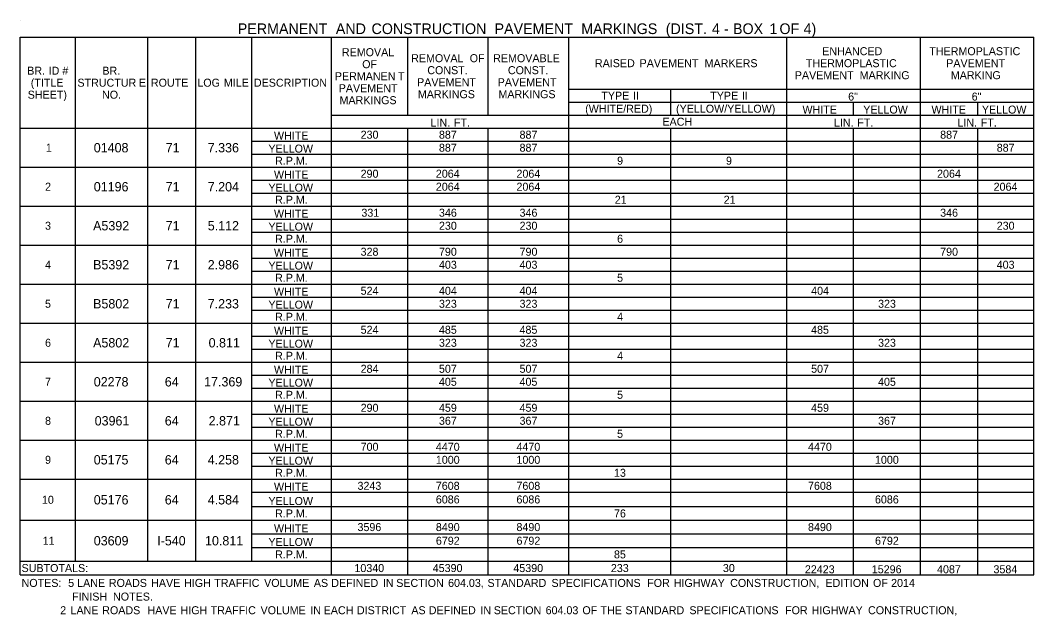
# Model space of a CAD drawing. Extents: x 540541 to 1930787, y -1948574 to 596640.
# Drawn here: x 540655 to 541415, y -1948048 to -1947601 of the extents above; entities that cross this region are included whole.
import ezdxf

# ---------------------------------------------------------------- set-up
doc = ezdxf.new("R2010")
doc.units = 0
doc.layers.add('Default', color=7, linetype='Continuous')
doc.layers.add('R_Border', color=7, linetype='Continuous')

msp = doc.modelspace()

# ---------------------------------------------------------------- linework, layer by layer
at = {"layer": 'Default'}
for p, q in [((540655.45, -1947614.17), (541415.47, -1947614.17)), ((540655.45, -1947614.17), (540888.97, -1947614.17)), ((540655.45, -1948017.33), (540655.45, -1947614.17)), ((540696.89, -1948007.1), (540696.89, -1947614.17)), ((540751, -1948007.1), (540751, -1947614.17)), ((540787.08, -1948007.1), (540787.08, -1947614.17)), ((540829, -1948007.1), (540829, -1947614.17)), ((540888.97, -1948017.33), (540888.97, -1947614.17)), ((540946, -1947614.17), (541066.9, -1947614.17)), ((540946, -1947672.67), (540946, -1947614.17)), ((541006.45, -1947672.67), (541006.45, -1947614.17)), ((541066.9, -1948017.33), (541066.9, -1947614.17)), ((541230.22, -1948017.33), (541230.22, -1947614.17)), ((541330.64, -1947672.67), (541330.64, -1947614.17)), ((541330.64, -1948017.33), (541330.64, -1947614.17)), ((541415.47, -1947653.17), (541415.47, -1947614.17)), ((541066.9, -1947653.17), (541415.47, -1947653.17)), ((541143.44, -1947672.67), (541143.44, -1947653.17)), ((541415.47, -1947672.67), (541415.47, -1947653.17)), ((541066.9, -1947662.92), (541415.47, -1947662.92)), ((541280.43, -1947672.67), (541280.43, -1947662.92)), ((541373.54, -1947672.67), (541373.54, -1947662.92)), ((540888.97, -1947672.67), (541415.47, -1947672.67)), ((541415.47, -1947682.42), (541415.47, -1947672.67)), ((540655.45, -1947682.42), (540829, -1947682.42)), ((540655.45, -1947682.42), (540787.08, -1947682.42)), ((540787.08, -1947682.42), (541415.47, -1947682.42)), ((540829, -1948007.1), (540829, -1947682.42)), ((540888.97, -1947701.92), (540888.97, -1947682.42)), ((540946, -1948007.1), (540946, -1947682.42)), ((540946, -1948017.33), (540946, -1947682.42)), ((541006.45, -1948007.1), (541006.45, -1947682.42)), ((541006.45, -1948017.33), (541006.45, -1947682.42)), ((541066.9, -1948007.1), (541066.9, -1947682.42)), ((541143.44, -1948017.33), (541143.44, -1947682.42)), ((541230.22, -1947731.17), (541230.22, -1947682.42)), ((541280.43, -1948007.1), (541280.43, -1947682.42)), ((541280.43, -1948017.33), (541280.43, -1947682.42)), ((541330.64, -1948007.1), (541330.64, -1947682.42)), ((541373.54, -1948017.33), (541373.54, -1947682.42)), ((541415.47, -1947799.42), (541415.47, -1947682.42)), ((540829, -1947692.17), (541415.47, -1947692.17)), ((540829, -1947701.92), (541415.47, -1947701.92)), ((541373.54, -1947740.92), (541373.54, -1947701.92)), ((540655.45, -1947711.67), (541415.47, -1947711.67)), ((540888.97, -1947731.17), (540888.97, -1947711.67)), ((540829, -1947721.42), (541415.47, -1947721.42)), ((540829, -1947731.17), (541415.47, -1947731.17)), ((540655.45, -1947740.92), (541415.47, -1947740.92)), ((540888.97, -1947760.42), (540888.97, -1947740.92)), ((541230.22, -1947789.67), (541230.22, -1947740.92)), ((540829, -1947750.67), (541415.47, -1947750.67)), ((540829, -1947760.42), (541415.47, -1947760.42)), ((541373.54, -1947799.42), (541373.54, -1947760.42)), ((540655.45, -1947770.17), (541415.47, -1947770.17)), ((540888.97, -1947789.67), (540888.97, -1947770.17)), ((540829, -1947779.92), (541415.47, -1947779.92)), ((540829, -1947789.67), (541415.47, -1947789.67)), ((540655.45, -1947799.42), (541415.47, -1947799.42)), ((540888.97, -1947818.92), (540888.97, -1947799.42)), ((541230.22, -1947848.17), (541230.22, -1947799.42)), ((541415.47, -1948017.33), (541415.47, -1947799.42)), ((540829, -1947809.17), (541415.47, -1947809.17)), ((540829, -1947818.92), (541415.47, -1947818.92)), ((541373.54, -1947857.92), (541373.54, -1947818.92)), ((540655.45, -1947828.67), (541415.47, -1947828.67)), ((540888.97, -1947848.17), (540888.97, -1947828.67)), ((540829, -1947838.42), (541415.47, -1947838.42)), ((540829, -1947848.17), (541415.47, -1947848.17)), ((540655.45, -1947857.92), (541415.47, -1947857.92)), ((540888.97, -1947877.42), (540888.97, -1947857.92)), ((541230.22, -1947906.67), (541230.22, -1947857.92)), ((540829, -1947867.67), (541415.47, -1947867.67)), ((540829, -1947877.42), (541415.47, -1947877.42)), ((541373.54, -1947916.42), (541373.54, -1947877.42)), ((540655.45, -1947887.17), (541415.47, -1947887.17)), ((540888.97, -1947906.67), (540888.97, -1947887.17)), ((540829, -1947896.92), (541415.47, -1947896.92)), ((540829, -1947906.67), (541415.47, -1947906.67)), ((540655.45, -1947916.42), (541415.47, -1947916.42)), ((540888.97, -1947935.92), (540888.97, -1947916.42)), ((541230.22, -1947966.15), (541230.22, -1947916.42)), ((540829, -1947926.17), (541415.47, -1947926.17)), ((540829, -1947935.92), (541415.47, -1947935.92)), ((541373.54, -1947976.38), (541373.54, -1947935.92)), ((540655.45, -1947945.67), (541415.47, -1947945.67)), ((540888.97, -1947966.15), (540888.97, -1947945.67)), ((540829, -1947955.42), (541415.47, -1947955.42)), ((540829, -1947966.15), (541415.47, -1947966.15)), ((540655.45, -1947976.38), (541415.47, -1947976.38)), ((540888.97, -1947996.86), (540888.97, -1947976.38)), ((541230.22, -1948007.1), (541230.22, -1947976.38)), ((540829, -1947986.62), (541415.47, -1947986.62)), ((540829, -1947996.86), (541415.47, -1947996.86)), ((541373.54, -1948017.33), (541373.54, -1947996.86)), ((540655.45, -1948007.1), (541415.47, -1948007.1)), ((540655.45, -1948017.33), (541415.47, -1948017.33))]:
    msp.add_line(p, q, dxfattribs=at)
at = {"layer": 'R_Border'}
msp.add_line((540655.45, -1947601.5), (540655.45, -1947601.5), dxfattribs=at)

# ---------------------------------------------------------------- texts
at = {"layer": 'Default'}
for s, height, p in [('PERMANENT', 8, (540818.55, -1947611.83)), (' AND', 8, (540889.12, -1947611.83)), (' CONSTRUCTION', 8, (540915.89, -1947611.83)), (' PAVEMENT', 8, (541008.15, -1947611.83)), (' MARKINGS', 8, (541073.14, -1947611.83)), (' (DIST.', 8, (541136.55, -1947611.83)), (' 4', 8, (541171.17, -1947611.83)), (' BOX', 8, (541186.98, -1947611.83)), (' 1', 8, (541214.29, -1947611.83)), (' OF', 8, (541221.8, -1947611.83)), (' 4)', 8, (541239.91, -1947611.83)), (' -', 8, (541180.23, -1947611.83)), ('REMOVAL', 6, (540896.65, -1947628.42)), ('ENHANCED', 6, (541256.88, -1947627.67)), ('THERMOPLASTIC', 6, (541337.17, -1947627.67)), ('REMOVAL', 6, (540948.6, -1947632.92)), (' OF', 6, (540990.27, -1947632.92)), ('REMOVABLE', 6, (541010.1, -1947632.92)), ('RAISED', 6, (541086.41, -1947636.67)), (' PAVEMENT', 6, (541117.67, -1947636.67)), (' MARKERS', 6, (541166.41, -1947636.67)), ('THERMOPLASTIC', 6, (541244.54, -1947636.67)), ('PAVEMENT', 6, (541349.85, -1947636.67)), ('BR.', 6, (540660.65, -1947642.3)), (' ID', 6, (540674.51, -1947642.3)), (' #', 6, (540684.8, -1947642.3)), ('BR.', 6, (540717.02, -1947642.3)), ('OF', 6, (540911.86, -1947637.42)), ('CONST.', 6, (540960.68, -1947641.92)), ('CONST.', 6, (541021.13, -1947641.92)), ('(TITLE', 6, (540663.34, -1947651.3)), ('STRUCTUR', 6, (540698.32, -1947651.3)), ('E', 6, (540744.39, -1947651.3)), ('ROUTE', 6, (540753.41, -1947651.3)), ('LOG', 6, (540788.24, -1947651.3)), (' MILE', 6, (540805.9, -1947651.3)), ('DESCRIPTION', 6, (540830.67, -1947651.3)), ('PERMANEN', 6, (540891.36, -1947646.42)), ('T', 6, (540938.67, -1947646.42)), ('PAVEMENT', 6, (540953.02, -1947650.92)), ('PAVEMENT', 6, (541013.47, -1947650.92)), ('PAVEMENT', 6, (541236.29, -1947645.67)), (' MARKING', 6, (541282.7, -1947645.67)), ('MARKING', 6, (541353.28, -1947645.67)), ('PAVEMENT', 6, (540894.28, -1947655.42)), ('SHEET)', 6, (540661.02, -1947660.3)), ('NO.', 6, (540716.78, -1947660.3)), ('MARKINGS', 6, (540894.87, -1947664.42)), ('MARKINGS', 6, (540953.61, -1947659.92)), ('MARKINGS', 6, (541014.06, -1947659.92)), ('TYPE', 6, (541091.21, -1947661.05)), (' II', 6, (541112.69, -1947661.05)), ('TYPE', 6, (541172.87, -1947661.05)), (' II', 6, (541194.35, -1947661.05)), ('6"', 6, (541276.32, -1947661.72)), ('6"', 6, (541368.94, -1947661.72)), ('(WHITE/RED)', 6, (541079.08, -1947670.8)), ('(YELLOW/YELLOW)', 6, (541147.23, -1947670.8)), ('WHITE', 6, (541242.03, -1947671.47)), ('YELLOW', 6, (541287.61, -1947671.47)), ('WHITE', 6, (541338.79, -1947671.47)), ('YELLOW', 6, (541376.58, -1947671.47)), ('LIN.', 6, (540963.14, -1947681.22)), (' FT.', 6, (540978.4, -1947681.22)), ('EACH', 6, (541137, -1947680.55)), ('LIN.', 6, (541265.64, -1947681.22)), (' FT.', 6, (541280.89, -1947681.22)), ('LIN.', 6, (541358.26, -1947681.22)), (' FT.', 6, (541373.52, -1947681.22)), ('WHITE', 6, (540845.7, -1947690.97)), ('230', 6, (540910.7, -1947690.3)), ('887', 6, (540969.43, -1947690.3)), ('887', 6, (541029.88, -1947690.3)), ('887', 6, (541345.29, -1947690.3)), ('1', 6, (540674.61, -1947700.05)), ('01408', 7, (540710.57, -1947700.55)), ('71', 7, (540764.5, -1947700.55)), ('7.336', 7, (540796.03, -1947700.55)), ('YELLOW', 6, (540841.56, -1947700.72)), ('887', 6, (540969.43, -1947700.05)), ('887', 6, (541029.88, -1947700.05)), ('887', 6, (541387.7, -1947700.05)), ('R.P.M.', 6, (540846.54, -1947709.8)), ('9', 6, (541103.03, -1947709.8)), ('9', 6, (541184.68, -1947709.8)), ('WHITE', 6, (540845.7, -1947720.22)), ('290', 6, (540910.7, -1947719.55)), ('2064', 6, (540967.11, -1947719.55)), ('2064', 6, (541027.56, -1947719.55)), ('2064', 6, (541342.97, -1947719.55)), ('2', 6, (540674.06, -1947729.3)), ('01196', 7, (540710.58, -1947729.8)), ('71', 7, (540764.5, -1947729.8)), ('7.204', 7, (540796.05, -1947729.8)), ('YELLOW', 6, (540841.56, -1947729.97)), ('2064', 6, (540967.11, -1947729.3)), ('2064', 6, (541027.56, -1947729.3)), ('2064', 6, (541385.39, -1947729.3)), ('R.P.M.', 6, (540846.54, -1947739.05)), ('21', 6, (541101.28, -1947739.05)), ('21', 6, (541182.94, -1947739.05)), ('WHITE', 6, (540845.7, -1947749.47)), ('331', 6, (540911.26, -1947748.8)), ('346', 6, (540969.43, -1947748.8)), ('346', 6, (541029.88, -1947748.8)), ('346', 6, (541345.29, -1947748.8)), ('A5392', 7, (540710.07, -1947759.05)), ('71', 7, (540764.5, -1947759.05)), ('5.112', 7, (540796.07, -1947759.05)), ('3', 6, (540674.03, -1947758.55)), ('YELLOW', 6, (540841.56, -1947759.22)), ('230', 6, (540969.44, -1947758.55)), ('230', 6, (541029.89, -1947758.55)), ('230', 6, (541387.71, -1947758.55)), ('R.P.M.', 6, (540846.54, -1947768.3)), ('6', 6, (541103.03, -1947768.3)), ('WHITE', 6, (540845.7, -1947778.72)), ('328', 6, (540910.68, -1947778.05)), ('790', 6, (540969.44, -1947778.05)), ('790', 6, (541029.89, -1947778.05)), ('790', 6, (541345.3, -1947778.05)), ('4', 6, (540674.05, -1947787.8)), ('B5392', 7, (540710.07, -1947788.3)), ('71', 7, (540764.5, -1947788.3)), ('2.986', 7, (540796.03, -1947788.3)), ('YELLOW', 6, (540841.56, -1947788.47)), ('403', 6, (540969.43, -1947787.8)), ('403', 6, (541029.88, -1947787.8)), ('403', 6, (541387.7, -1947787.8)), ('R.P.M.', 6, (540846.54, -1947797.55)), ('5', 6, (541103.01, -1947797.55)), ('WHITE', 6, (540845.7, -1947807.97)), ('524', 6, (540910.7, -1947807.3)), ('404', 6, (540969.44, -1947807.3)), ('404', 6, (541029.89, -1947807.3)), ('404', 6, (541248.54, -1947807.3)), ('5', 6, (540674.01, -1947817.05)), ('B5802', 7, (540710.07, -1947817.55)), ('71', 7, (540764.5, -1947817.55)), ('7.233', 7, (540796.03, -1947817.55)), ('YELLOW', 6, (540841.56, -1947817.72)), ('323', 6, (540969.43, -1947817.05)), ('323', 6, (541029.88, -1947817.05)), ('323', 6, (541298.73, -1947817.05)), ('R.P.M.', 6, (540846.54, -1947826.8)), ('4', 6, (541103.05, -1947826.8)), ('WHITE', 6, (540845.7, -1947837.22)), ('524', 6, (540910.7, -1947836.55)), ('485', 6, (540969.4, -1947836.55)), ('485', 6, (541029.85, -1947836.55)), ('485', 6, (541248.5, -1947836.55)), ('6', 6, (540674.03, -1947846.3)), ('A5802', 7, (540710.07, -1947846.8)), ('71', 7, (540764.5, -1947846.8)), ('0.811', 7, (540796.71, -1947846.8)), ('YELLOW', 6, (540841.56, -1947846.97)), ('323', 6, (540969.43, -1947846.3)), ('323', 6, (541029.88, -1947846.3)), ('323', 6, (541298.73, -1947846.3)), ('R.P.M.', 6, (540846.54, -1947856.05)), ('4', 6, (541103.05, -1947856.05)), ('WHITE', 6, (540845.7, -1947866.47)), ('284', 6, (540910.7, -1947865.8)), ('507', 6, (540969.43, -1947865.8)), ('507', 6, (541029.88, -1947865.8)), ('507', 6, (541248.52, -1947865.8)), ('7', 6, (540674.03, -1947875.55)), ('02278', 7, (540710.57, -1947876.05)), ('64', 7, (540763.84, -1947876.05)), ('17.369', 7, (540793.31, -1947876.05)), ('YELLOW', 6, (540841.56, -1947876.22)), ('405', 6, (540969.4, -1947875.55)), ('405', 6, (541029.85, -1947875.55)), ('405', 6, (541298.71, -1947875.55)), ('R.P.M.', 6, (540846.54, -1947885.3)), ('5', 6, (541103.01, -1947885.3)), ('290', 6, (540910.7, -1947895.05)), ('459', 6, (540969.42, -1947895.05)), ('459', 6, (541029.87, -1947895.05)), ('459', 6, (541248.52, -1947895.05)), ('WHITE', 6, (540845.7, -1947895.72)), ('8', 6, (540674.03, -1947904.8)), ('03961', 7, (540711.25, -1947905.3)), ('64', 7, (540763.84, -1947905.3)), ('2.871', 7, (540796.71, -1947905.3)), ('YELLOW', 6, (540841.56, -1947905.47)), ('367', 6, (540969.43, -1947904.8)), ('367', 6, (541029.88, -1947904.8)), ('367', 6, (541298.73, -1947904.8)), ('R.P.M.', 6, (540846.54, -1947914.55)), ('5', 6, (541103.01, -1947914.55)), ('WHITE', 6, (540845.7, -1947924.97)), ('700', 6, (540910.7, -1947924.3)), ('4470', 6, (540967.11, -1947924.3)), ('4470', 6, (541027.56, -1947924.3)), ('4470', 6, (541246.2, -1947924.3)), ('9', 6, (540674.03, -1947934.05)), ('05175', 7, (540710.55, -1947934.55)), ('64', 7, (540763.84, -1947934.55)), ('4.258', 7, (540796.03, -1947934.55)), ('YELLOW', 6, (540841.56, -1947934.72)), ('1000', 6, (540967.11, -1947934.05)), ('1000', 6, (541027.56, -1947934.05)), ('1000', 6, (541296.42, -1947934.05)), ('R.P.M.', 6, (540846.54, -1947943.8)), ('13', 6, (541100.7, -1947943.8)), ('WHITE', 6, (540845.7, -1947954.22)), ('3243', 6, (540908.35, -1947953.55)), ('7608', 6, (540967.09, -1947953.55)), ('7608', 6, (541027.54, -1947953.55)), ('7608', 6, (541246.19, -1947953.55)), ('05176', 7, (540710.58, -1947964.53)), ('64', 7, (540763.84, -1947964.53)), ('4.584', 7, (540796.05, -1947964.53)), ('10', 6, (540671.71, -1947964.03)), ('YELLOW', 6, (540841.56, -1947964.95)), ('6086', 6, (540967.1, -1947963.78)), ('6086', 6, (541027.55, -1947963.78)), ('6086', 6, (541296.4, -1947963.78)), ('R.P.M.', 6, (540846.54, -1947974.27)), ('76', 6, (541100.7, -1947974.27)), ('WHITE', 6, (540845.7, -1947985.42)), ('3596', 6, (540908.35, -1947984.5)), ('8490', 6, (540967.11, -1947984.5)), ('8490', 6, (541027.56, -1947984.5)), ('8490', 6, (541246.2, -1947984.5)), ('11', 6, (540672.28, -1947994.74)), ('03609', 7, (540710.57, -1947995.24)), ('I-540', 7, (540758.14, -1947995.24)), ('10.811', 7, (540793.99, -1947995.24)), ('YELLOW', 6, (540841.56, -1947995.66)), ('6792', 6, (540967.13, -1947994.74)), ('6792', 6, (541027.58, -1947994.74)), ('6792', 6, (541296.44, -1947994.74)), ('R.P.M.', 6, (540846.54, -1948004.98)), ('85', 6, (541100.68, -1948004.98)), ('SUBTOTALS:', 6, (540656.43, -1948015.22)), ('10340', 6, (540906.04, -1948015.22)), ('45390', 6, (540964.78, -1948015.22)), ('45390', 6, (541025.23, -1948015.22)), ('233', 6, (541098.36, -1948015.22)), ('30', 6, (541182.37, -1948015.22)), ('22423', 6, (541243.85, -1948016.13)), ('15296', 6, (541294.03, -1948016.13)), ('4087', 6, (541342.96, -1948016.13)), ('3584', 6, (541385.28, -1948016.13)), ('NOTES:', 6, (540656.43, -1948026.37)), ('  5', 6, (540686.91, -1948026.37)), (' LANE', 6, (540695.89, -1948026.37)), (' ROADS', 6, (540719.67, -1948026.37)), (' HAVE', 6, (540751.38, -1948026.37)), (' HIGH', 6, (540776.09, -1948026.37)), (' TRAFFIC', 6, (540798.7, -1948026.37)), (' VOLUME', 6, (540836.09, -1948026.37)), (' AS', 6, (540873.37, -1948026.37)), (' DEFINED', 6, (540886.45, -1948026.37)), (' IN', 6, (540925.13, -1948026.37)), (' SECTION', 6, (540935.15, -1948026.37)), (' 604.03,', 6, (540974.06, -1948026.37)), (' STANDARD', 6, (541003.6, -1948026.37)), (' SPECIFICATIONS', 6, (541051.6, -1948026.37)), (' FOR', 6, (541123.37, -1948026.37)), (' HIGHWAY', 6, (541143.28, -1948026.37)), (' CONSTRUCTION,', 6, (541185.6, -1948026.37)), (' EDITION', 6, (541257.05, -1948026.37)), (' OF', 6, (541292.69, -1948026.37)), (' 2014', 6, (541306.28, -1948026.37)), ('                 FINISH', 6, (540656.43, -1948036.61)), (' NOTES.', 6, (540722.8, -1948036.61)), ('             2', 6, (540656.43, -1948046.85)), (' LANE', 6, (540690.91, -1948046.85)), (' ROADS', 6, (540714.69, -1948046.85)), ('  HAVE', 6, (540746.39, -1948046.85)), (' HIGH', 6, (540773.43, -1948046.85)), (' TRAFFIC', 6, (540796.04, -1948046.85)), (' VOLUME', 6, (540833.43, -1948046.85)), (' IN', 6, (540870.72, -1948046.85)), (' EACH', 6, (540880.74, -1948046.85)), (' DISTRICT', 6, (540905.69, -1948046.85)), (' AS', 6, (540946.5, -1948046.85)), (' DEFINED', 6, (540959.58, -1948046.85)), (' IN', 6, (540998.26, -1948046.85)), (' SECTION', 6, (541008.28, -1948046.85)), (' 604.03', 6, (541047.19, -1948046.85)), (' OF', 6, (541074.77, -1948046.85)), (' THE', 6, (541088.35, -1948046.85)), (' STANDARD', 6, (541107, -1948046.85)), (' SPECIFICATIONS', 6, (541155, -1948046.85)), (' FOR', 6, (541226.77, -1948046.85)), (' HIGHWAY', 6, (541246.68, -1948046.85)), (' CONSTRUCTION,', 6, (541289, -1948046.85))]:
    msp.add_text(s, height=height, dxfattribs=at).set_placement(p)

doc.saveas('drawing.dxf')
